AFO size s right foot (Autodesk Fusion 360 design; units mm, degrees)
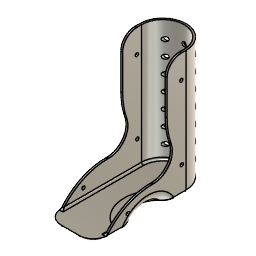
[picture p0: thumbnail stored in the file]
part number: 2025-10-02-12-56-12-317
sketch "Sketch1" plane through (0, 0, 0) normal (0, 0, 1) x axis (1, 0, 0)
  line L1 (-24.5, -98.2) -> (-24.5, 0)
  line L2 (24.5, -98.2) -> (-24.5, -98.2)
  line L3 (24.5, 0) -> (24.5, -98.2)
  line L4 (-22.5, 0) -> (-22.5, -98.2)
  line L5 (22.5, 0) -> (22.5, -98.2)
  line L6 (-22.5, 0) -> (-24.5, 0)
  line L7 (24.5, 0) -> (22.5, 0)
  line L8 (-22.5, -83.2) -> (-24.5, -83.2)
  line L9 (-9.5, -98.2) -> (-9.5, -83.2)
  line L10 (9.5, -98.2) -> (9.5, -83.2)
  line L11 (9.5, -98.2) -> (-9.5, -98.2)
  line L12 (24.6995, -83.2) -> (-16.3005, -83.2)
  circle C1 centre (0, 0) radius 24.5
  circle C2 centre (0, 0) radius 22.5
  circle C3 centre (-9.5, -83.2) radius 15
  circle C4 centre (9.5, -83.2) radius 15
  circle C5 centre (-9.5, -83.2) radius 13
  circle C6 centre (9.5, -83.2) radius 13
  point P1 (0, 0)
  point P2 (0, 0)
  point P3 (-24.5, 0)
  point P6 (24.5, 0)
  point P7 (0, 0)
  point P8 (-22.5, 0)
  point P10 (22.5, 0)
  point P11 (22.5, -98.2)
  point P9 (-22.5, -98.2)
  point P16 (-24.5, -83.2)
  point P17 (-22.5, -83.2)
  point P12 (-9.5, -83.2)
  point P18 (-9.5, -83.2)
  point P19 (-9.5, -98.2)
  point P15 (9.5, -83.2)
  point P20 (9.5, -83.2)
  point P21 (9.5, -98.2)
  point P13 (9.5, -83.2)
  coincident P1 P2
  coincident C1 P3
  tangent C1 L1
  vertical L1
  perpendicular L1 L2
  coincident C1 P6
  tangent C1 L3
  perpendicular L2 L3
  coincident P1 P7
  vertical L4
  coincident C2 P8
  vertical L5
  coincident C2 P10
  perpendicular L4 L6
  perpendicular L3 L7
  coincident L2 P11
  coincident L2 P9
  tangent L3 C4
  tangent L1 C3
  tangent L2 C3
  tangent L2 C4
  concentric C3 C5
  tangent L4 C5
  concentric C4 C6
  tangent L5 C6
  coincident C3 P16
  coincident C5 P17
  coincident L4 P17
  perpendicular L4 L8
  coincident P12 P18
  coincident L2 P19
  coincident C3 P19
  perpendicular L2 L9
  coincident P15 P20
  coincident L2 P21
  coincident C4 P21
  perpendicular L2 L10
  perpendicular L3 L12
  coincident P13 L12
  dimension "d2" diameter C1 = 49 (= "d57 + ( 2 * 2 ) * 1 mm")
  dimension "d4" distance P2 L2 = 98.2
  dimension "d57" diameter C2 = 45
  dimension "d73" diameter C3 = 30
  dimension "d74" diameter C4 = 30
extrude "Extrude1" new body sketch "Sketch1" profile of C1 L1 L3 L4 L5 L6 L7 C3 C4 L8 L12 along normal blind 25
extrude "Extrude2" add sketch "Sketch1" profile of C1 C2 L4 L5 C3 C4 C5 C6 L8 L9 L10 L12 along normal blind 2
extrude "Extrude8" add sketch "Sketch1" profile of L2 C3 C4 L11 along normal blind 2
extrude "Extrude3" add sketch "Sketch1" profile of C1 C2 L6 L7 along normal blind 130
work_plane "WorkPlane3" AlongDistance 40
sphere_primitive "SpherePrimitive3" Diameter 55
move_face "MoveFace3"
boundary_fill "BoundaryFill2"
offset_faces "OffsetFaces3" distance 2
shell "Shell5" innerThickness 2
fillet "Fillet31" radius 25
extrude "Extrude15" cut of existing geometry blind -6
work_plane "WorkPlane1" RotateAngle -90
sketch "Sketch2" plane through (24.5, 0, 0) normal (1, 0, 0) x axis (0, 1, 0)
  line L1 (0, 130) -> (-20, 130)
  line L2 (0, 25) -> (0, 130)
  line L3 (-20, 40) -> (-20, 130)
  line L4 (0, 25) -> (-20, 40)
  circle C1 centre (-5, 105) radius 1.75
  point P2 (0, 25)
  point P6 (0, 25)
  point P4 (0, 130)
  point P7 (0, 130)
  point P3 (-20, 130)
  point P5 (-20, 40)
  point P8 (-5, 105)
  horizontal L1
  perpendicular L1 L2
  perpendicular L1 L3
  coincident P2 P6
  coincident P4 P7
  dimension "d25" distance P3 P4 = 20
  dimension "d28" distance P3 P5 = 90
  dimension "d43" diameter C1 = 3.5
  dimension "d45" distance L3 P8 = 15
  dimension "d47" distance L1 P8 = 25
extrude "Extrude11" add sketch "Sketch2" against normal blind 2
mirror "Mirror1" mirrorStitchTolerance 0.1
work_plane "WorkPlane4" AlongDistance 24.5 (= "22.5 mm + 2 mm")
sketch "Sketch9" plane through (0, 24.5, 0) normal (0, 1, 0) x axis (1, 0, 0)
  circle C1 centre (0, -16) radius 2.25
  circle C2 centre (0, -32) radius 2.25
  circle C3 centre (0, -48) radius 2.25
  circle C4 centre (0, -64) radius 2.25
  circle C5 centre (0, -96) radius 2.25
  circle C6 centre (0, -80) radius 2.25
  circle C7 centre (0, -112) radius 2.25
  point P2 (0, -16)
  point P8 (0, 0)
  point P3 (0, -32)
  point P4 (0, -48)
  point P5 (0, -64)
  point P7 (0, -80)
  point P6 (0, -96)
  point P9 (0, -112)
  dimension "d123" diameter C1 = 4.5
  dimension "d124" diameter C2 = 4.5
  dimension "d125" diameter C3 = 4.5
  dimension "d126" diameter C4 = 4.5
  dimension "d127" diameter C5 = 4.5
  dimension "d128" diameter C6 = 4.5
  dimension "d129" distance P2 P8 = 16
  dimension "d130" distance P2 P3 = 16
  dimension "d131" distance P3 P4 = 16
  dimension "d132" distance P4 P5 = 16 (= "d131")
  dimension "d133" distance P5 P7 = 16 (= "d131")
  dimension "d134" distance P6 P7 = 16 (= "d131")
  dimension "d184" diameter C7 = 4.5
  dimension "d239" distance P6 P9 = 16
extrude "Extrude12" cut sketch "Sketch9" against normal blind 40
path_pattern "PathPattern2" PathPatternDelta 74
fillet "Fillet28" radius 60
fillet "Fillet18" radius 80
fillet "Fillet32" radius 10
fillet "Fillet33" radius 10
fillet "Fillet34" radius 20
fillet "Fillet35" radius 15
fillet "Fillet36" radius 2
fillet "Fillet37" radius 4
hole "Hole3" HoleDepth 90 HoleDiameter 3.5 TipAngle 118
hole "Hole4" HoleDepth 90 HoleDiameter 3.5 TipAngle 118
fillet "Fillet44" radius 2
fillet "Fillet46" radius 5
fillet "Fillet47" radius 5
fillet "Fillet48" radius 2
